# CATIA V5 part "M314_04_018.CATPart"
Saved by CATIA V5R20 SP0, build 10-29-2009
Part number: M314_04_018
Source: Unknown
Property "ARTICLENO": "M314-04-018"
Property "B": "45.000"
Property "BOMINFO": "M314-04-018"
Property "CODE": "M314-04-018"
Property "D": "15.000"
Property "FINALFORCE": "294.1 (30)"
Property "INITIALFORCE": "49.0 (5)"
Property "K": "20.000"
Property "L": "70.000"
Property "LINA": "M314-04-018"
Property "M": "M30x3.5"
Property "NB": "M314-04-018"
Property "NBSYN": "$CODE."
Property "NN": "M314-04"
Property "NT": "Spring Plunger"
Property "SUPPLIER": "CF"
Property "SW": "12.000"
Bounding box of the stored display mesh (mm): x -15 to 15, y 0 to 90, z -15 to 15
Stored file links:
  C:\Users\Utente\Desktop\3D files M314\M314_04_018.CATPart
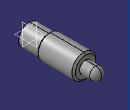
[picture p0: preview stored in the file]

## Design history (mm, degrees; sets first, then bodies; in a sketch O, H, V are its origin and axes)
Body1 "Geometry.1" (main body)
  Solid1 "M314_04_018.catpart": solid without history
